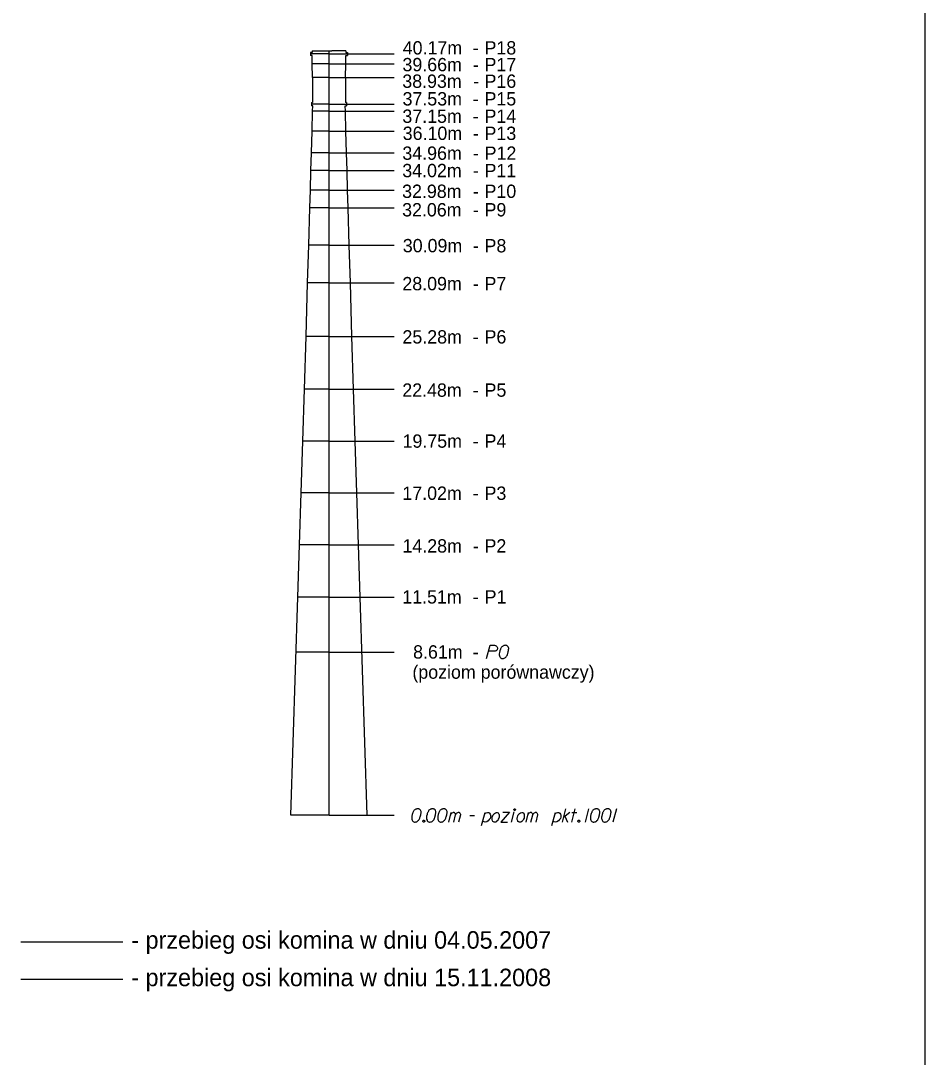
# Model space of a CAD drawing. Extents: x 138 to 6653, y -177 to 1520.
# Drawn here: x 387.54 to 398.01, y -57.33 to -45.34 of the extents above; entities that cross this region are included whole.
import ezdxf

# ---------------------------------------------------------------- set-up
doc = ezdxf.new("R2010")
doc.units = 0
for name, color, linetype in [('15 listopad 2008', 7, 'Continuous'), ('Opisy', 7, 'Continuous'), ('Ramka do drukowania', 7, 'Continuous')]:
    doc.layers.add(name, color=color, linetype=linetype)

msp = doc.modelspace()

# ---------------------------------------------------------------- linework, layer by layer
at = {"layer": '15 listopad 2008'}
for p, q in [((387.538, -55.997), (388.719, -55.997)), ((387.538, -56.429), (388.719, -56.429))]:
    msp.add_line(p, q, dxfattribs=at)
at = {"layer": 'Opisy'}
for p, q in [((390.893, -45.703), (390.893, -45.721)), ((390.91, -45.703), (390.893, -45.703)), ((390.91, -45.684), (390.91, -45.703)), ((390.91, -45.684), (391.137, -45.684)), ((391.106, -54.531), (391.106, -45.684)), ((391.302, -45.684), (391.137, -45.684)), ((391.302, -45.684), (391.302, -45.703)), ((391.302, -45.703), (391.319, -45.703)), ((391.319, -45.703), (391.319, -45.721)), ((391.106, -45.721), (390.893, -45.721)), ((390.893, -45.721), (390.893, -45.74)), ((390.91, -45.74), (390.893, -45.74)), ((390.91, -45.834), (390.91, -45.74)), ((391.106, -45.721), (391.859, -45.721)), ((391.302, -45.74), (391.319, -45.74)), ((391.302, -45.834), (391.302, -45.74)), ((391.319, -45.721), (391.319, -45.74)), ((391.106, -45.834), (390.91, -45.834)), ((390.916, -45.994), (390.91, -45.834)), ((391.106, -45.834), (391.859, -45.834)), ((391.296, -45.994), (391.302, -45.834)), ((391.106, -45.994), (390.916, -45.994)), ((390.916, -45.994), (390.916, -46.282)), ((391.106, -45.994), (391.859, -45.994)), ((391.296, -45.994), (391.296, -46.282)), ((390.903, -46.282), (390.903, -46.301)), ((390.903, -46.282), (390.916, -46.282)), ((391.106, -46.301), (390.903, -46.301)), ((390.903, -46.301), (390.903, -46.321)), ((391.106, -46.301), (391.859, -46.301)), ((391.309, -46.282), (391.296, -46.282)), ((391.309, -46.282), (391.309, -46.301)), ((391.309, -46.301), (391.309, -46.321)), ((390.918, -46.321), (390.903, -46.321)), ((390.91, -46.615), (390.916, -46.384)), ((390.916, -46.384), (390.918, -46.321)), ((391.106, -46.384), (390.916, -46.384)), ((391.106, -46.384), (391.859, -46.384)), ((391.296, -46.384), (391.294, -46.321)), ((391.294, -46.321), (391.309, -46.321)), ((391.302, -46.615), (391.296, -46.384)), ((390.903, -46.866), (390.91, -46.615)), ((391.106, -46.615), (390.91, -46.615)), ((391.106, -46.615), (391.859, -46.615)), ((391.309, -46.866), (391.302, -46.615)), ((390.897, -47.071), (390.903, -46.866)), ((391.106, -46.866), (390.903, -46.866)), ((391.106, -46.866), (391.859, -46.866)), ((391.315, -47.071), (391.309, -46.866)), ((390.891, -47.299), (390.897, -47.071)), ((391.106, -47.071), (390.897, -47.071)), ((391.106, -47.071), (391.859, -47.071)), ((391.321, -47.299), (391.315, -47.071)), ((390.884, -47.501), (390.891, -47.299)), ((391.106, -47.299), (390.891, -47.299)), ((391.106, -47.299), (391.859, -47.299)), ((391.329, -47.501), (391.321, -47.299)), ((390.871, -47.933), (390.884, -47.501)), ((391.106, -47.501), (390.884, -47.501)), ((391.106, -47.501), (391.859, -47.501)), ((391.341, -47.933), (391.329, -47.501)), ((390.858, -48.371), (390.871, -47.933)), ((391.106, -47.933), (390.871, -47.933)), ((391.106, -47.933), (391.859, -47.933)), ((391.354, -48.371), (391.341, -47.933)), ((390.841, -48.989), (390.858, -48.371)), ((391.106, -48.371), (390.858, -48.371)), ((391.106, -48.371), (391.859, -48.371)), ((391.371, -48.989), (391.354, -48.371)), ((390.821, -49.601), (390.841, -48.989)), ((391.106, -48.989), (390.841, -48.989)), ((391.106, -48.989), (391.859, -48.989)), ((391.391, -49.601), (391.371, -48.989)), ((390.802, -50.2), (390.821, -49.601)), ((391.106, -49.601), (390.821, -49.601)), ((391.106, -49.601), (391.859, -49.601)), ((391.41, -50.2), (391.391, -49.601)), ((390.784, -50.798), (390.802, -50.2)), ((391.106, -50.2), (390.802, -50.2)), ((391.106, -50.2), (391.859, -50.2)), ((391.428, -50.798), (391.41, -50.2)), ((390.765, -51.4), (390.784, -50.798)), ((391.106, -50.798), (390.784, -50.798)), ((391.106, -50.798), (391.859, -50.798)), ((391.447, -51.4), (391.428, -50.798)), ((390.745, -52.006), (390.765, -51.4)), ((391.106, -51.4), (390.765, -51.4)), ((391.106, -51.4), (391.859, -51.4)), ((391.467, -52.006), (391.447, -51.4)), ((390.663, -54.531), (390.745, -52.006)), ((391.106, -52.006), (390.745, -52.006)), ((391.106, -52.006), (391.859, -52.006)), ((391.549, -54.531), (391.467, -52.006)), ((391.106, -52.643), (390.725, -52.643)), ((391.106, -52.643), (391.859, -52.643)), ((391.106, -54.531), (390.663, -54.531)), ((391.106, -54.531), (391.859, -54.531))]:
    msp.add_line(p, q, dxfattribs=at)
for points in [[(392.928, -52.718), (392.97, -52.563), (393.022, -52.563), (393.029, -52.565), (393.033, -52.566), (393.04, -52.57), (393.045, -52.573), (393.048, -52.578), (393.052, -52.584), (393.055, -52.593), (393.056, -52.6), (393.055, -52.606), (393.053, -52.611), (393.051, -52.616), (393.048, -52.619), (393.045, -52.624), (393.04, -52.628), (393.036, -52.63), (393.03, -52.633), (393.024, -52.634), (392.951, -52.634)], [(393.149, -52.563), (393.147, -52.563), (393.14, -52.565), (393.135, -52.566), (393.131, -52.567), (393.125, -52.57), (393.118, -52.573), (393.112, -52.577), (393.106, -52.582), (393.102, -52.587), (393.098, -52.593), (393.095, -52.599), (393.091, -52.606), (393.089, -52.611), (393.086, -52.618), (393.082, -52.63), (393.079, -52.648), (393.076, -52.663), (393.076, -52.676), (393.078, -52.686), (393.082, -52.697), (393.086, -52.703), (393.092, -52.71), (393.099, -52.715), (393.103, -52.716), (393.11, -52.718), (393.116, -52.718), (393.126, -52.716), (393.135, -52.714), (393.141, -52.71), (393.149, -52.704), (393.153, -52.701), (393.158, -52.696), (393.161, -52.691), (393.164, -52.687), (393.166, -52.681), (393.167, -52.679), (393.17, -52.673), (393.172, -52.665), (393.175, -52.658), (393.176, -52.653), (393.177, -52.65), (393.178, -52.645), (393.181, -52.634), (393.182, -52.628), (393.183, -52.622), (393.184, -52.613), (393.186, -52.602), (393.186, -52.599), (393.184, -52.594), (393.183, -52.589), (393.18, -52.582), (393.176, -52.577), (393.172, -52.573), (393.167, -52.57), (393.163, -52.567), (393.159, -52.566), (393.155, -52.565), (393.149, -52.563)], [(392.135, -54.456), (392.133, -54.456), (392.126, -54.457), (392.121, -54.458), (392.117, -54.46), (392.111, -54.462), (392.104, -54.466), (392.098, -54.469), (392.092, -54.474), (392.088, -54.479), (392.084, -54.485), (392.081, -54.491), (392.077, -54.498), (392.075, -54.503), (392.072, -54.51), (392.069, -54.523), (392.065, -54.541), (392.063, -54.555), (392.063, -54.569), (392.064, -54.578), (392.069, -54.589), (392.072, -54.595), (392.078, -54.603), (392.086, -54.608), (392.089, -54.609), (392.097, -54.61), (392.103, -54.61), (392.112, -54.609), (392.121, -54.606), (392.127, -54.603), (392.135, -54.597), (392.139, -54.593), (392.144, -54.588), (392.147, -54.583), (392.15, -54.58), (392.152, -54.574), (392.154, -54.571), (392.156, -54.565), (392.158, -54.558), (392.161, -54.551), (392.162, -54.546), (392.163, -54.542), (392.164, -54.537), (392.167, -54.526), (392.168, -54.52), (392.169, -54.514), (392.171, -54.506), (392.172, -54.495), (392.172, -54.491), (392.171, -54.486), (392.169, -54.481), (392.166, -54.474), (392.162, -54.469), (392.158, -54.466), (392.154, -54.462), (392.149, -54.46), (392.145, -54.458), (392.141, -54.457), (392.135, -54.456)], [(392.306, -54.456), (392.304, -54.456), (392.297, -54.457), (392.292, -54.458), (392.288, -54.46), (392.282, -54.462), (392.275, -54.466), (392.269, -54.469), (392.263, -54.474), (392.259, -54.479), (392.256, -54.485), (392.252, -54.491), (392.248, -54.498), (392.246, -54.503), (392.243, -54.51), (392.24, -54.523), (392.236, -54.541), (392.234, -54.555), (392.234, -54.569), (392.235, -54.578), (392.24, -54.589), (392.243, -54.595), (392.249, -54.603), (392.257, -54.608), (392.26, -54.609), (392.268, -54.61), (392.274, -54.61), (392.283, -54.609), (392.292, -54.606), (392.298, -54.603), (392.306, -54.597), (392.31, -54.593), (392.315, -54.588), (392.319, -54.583), (392.321, -54.58), (392.323, -54.574), (392.325, -54.571), (392.327, -54.565), (392.33, -54.558), (392.332, -54.551), (392.333, -54.546), (392.334, -54.542), (392.336, -54.537), (392.338, -54.526), (392.339, -54.52), (392.34, -54.514), (392.342, -54.506), (392.343, -54.495), (392.343, -54.491), (392.342, -54.486), (392.34, -54.481), (392.337, -54.474), (392.333, -54.469), (392.33, -54.466), (392.325, -54.462), (392.32, -54.46), (392.316, -54.458), (392.313, -54.457), (392.306, -54.456)], [(392.436, -54.456), (392.434, -54.456), (392.427, -54.457), (392.422, -54.458), (392.418, -54.46), (392.412, -54.462), (392.405, -54.466), (392.399, -54.469), (392.393, -54.474), (392.389, -54.479), (392.385, -54.485), (392.382, -54.491), (392.378, -54.498), (392.376, -54.503), (392.373, -54.51), (392.37, -54.523), (392.366, -54.541), (392.364, -54.555), (392.364, -54.569), (392.365, -54.578), (392.37, -54.589), (392.373, -54.595), (392.379, -54.603), (392.387, -54.608), (392.39, -54.609), (392.398, -54.61), (392.404, -54.61), (392.413, -54.609), (392.422, -54.606), (392.428, -54.603), (392.436, -54.597), (392.44, -54.593), (392.445, -54.588), (392.448, -54.583), (392.451, -54.58), (392.453, -54.574), (392.455, -54.571), (392.457, -54.565), (392.459, -54.558), (392.462, -54.551), (392.463, -54.546), (392.464, -54.542), (392.465, -54.537), (392.468, -54.526), (392.469, -54.52), (392.47, -54.514), (392.472, -54.506), (392.473, -54.495), (392.473, -54.491), (392.472, -54.486), (392.47, -54.481), (392.467, -54.474), (392.463, -54.469), (392.459, -54.466), (392.455, -54.462), (392.45, -54.46), (392.446, -54.458), (392.442, -54.457), (392.436, -54.456)], [(393.251, -54.456), (393.257, -54.456), (393.261, -54.458), (393.264, -54.463), (393.264, -54.469), (393.261, -54.474), (393.257, -54.477), (393.251, -54.477), (393.247, -54.474), (393.244, -54.469), (393.244, -54.463), (393.247, -54.458), (393.251, -54.456)], [(393.807, -54.61), (393.848, -54.456)], [(393.915, -54.61), (393.955, -54.456)], [(394.11, -54.456), (394.069, -54.61)], [(394.204, -54.456), (394.201, -54.456), (394.194, -54.457), (394.189, -54.458), (394.186, -54.46), (394.18, -54.462), (394.172, -54.466), (394.166, -54.469), (394.16, -54.474), (394.156, -54.479), (394.153, -54.485), (394.149, -54.491), (394.146, -54.498), (394.143, -54.503), (394.141, -54.51), (394.137, -54.523), (394.133, -54.541), (394.131, -54.555), (394.131, -54.569), (394.132, -54.578), (394.137, -54.589), (394.141, -54.595), (394.147, -54.603), (394.154, -54.608), (394.158, -54.609), (394.165, -54.61), (394.171, -54.61), (394.181, -54.609), (394.189, -54.606), (394.195, -54.603), (394.204, -54.597), (394.207, -54.593), (394.212, -54.588), (394.216, -54.583), (394.218, -54.58), (394.221, -54.574), (394.222, -54.571), (394.224, -54.565), (394.227, -54.558), (394.229, -54.551), (394.231, -54.546), (394.232, -54.542), (394.233, -54.537), (394.235, -54.526), (394.237, -54.52), (394.238, -54.514), (394.239, -54.506), (394.24, -54.495), (394.24, -54.491), (394.239, -54.486), (394.238, -54.481), (394.234, -54.474), (394.231, -54.469), (394.227, -54.466), (394.222, -54.462), (394.217, -54.46), (394.214, -54.458), (394.21, -54.457), (394.204, -54.456)], [(394.334, -54.456), (394.331, -54.456), (394.324, -54.457), (394.319, -54.458), (394.315, -54.46), (394.309, -54.462), (394.302, -54.466), (394.296, -54.469), (394.29, -54.474), (394.286, -54.479), (394.283, -54.485), (394.279, -54.491), (394.275, -54.498), (394.273, -54.503), (394.271, -54.51), (394.267, -54.523), (394.263, -54.541), (394.261, -54.555), (394.261, -54.569), (394.262, -54.578), (394.267, -54.589), (394.271, -54.595), (394.277, -54.603), (394.284, -54.608), (394.288, -54.609), (394.295, -54.61), (394.301, -54.61), (394.311, -54.609), (394.319, -54.606), (394.325, -54.603), (394.334, -54.597), (394.337, -54.593), (394.342, -54.588), (394.346, -54.583), (394.348, -54.58), (394.351, -54.574), (394.352, -54.571), (394.354, -54.565), (394.357, -54.558), (394.359, -54.551), (394.36, -54.546), (394.362, -54.542), (394.363, -54.537), (394.365, -54.526), (394.366, -54.52), (394.368, -54.514), (394.369, -54.506), (394.37, -54.495), (394.37, -54.491), (394.369, -54.486), (394.368, -54.481), (394.364, -54.474), (394.36, -54.469), (394.357, -54.466), (394.352, -54.462), (394.347, -54.46), (394.343, -54.458), (394.34, -54.457), (394.334, -54.456)], [(394.432, -54.456), (394.391, -54.61)], [(392.493, -54.61), (392.521, -54.5)], [(392.514, -54.529), (392.52, -54.515), (392.526, -54.508), (392.533, -54.503), (392.541, -54.5), (392.546, -54.497), (392.553, -54.497), (392.555, -54.498), (392.56, -54.503), (392.565, -54.509), (392.569, -54.52), (392.57, -54.526), (392.576, -54.515), (392.583, -54.508), (392.591, -54.503), (392.598, -54.5), (392.604, -54.497), (392.61, -54.497), (392.615, -54.498), (392.618, -54.503), (392.622, -54.509), (392.626, -54.52), (392.627, -54.526), (392.606, -54.61)], [(392.549, -54.61), (392.57, -54.526)], [(392.736, -54.532), (392.789, -54.532)], [(392.871, -54.65), (392.912, -54.498)], [(392.909, -54.512), (392.921, -54.502), (392.939, -54.498), (392.954, -54.501), (392.963, -54.508), (392.971, -54.518), (392.975, -54.531), (392.977, -54.543), (392.974, -54.554), (392.971, -54.568), (392.961, -54.582), (392.949, -54.595), (392.931, -54.608), (392.915, -54.61), (392.9, -54.609), (392.884, -54.6)], [(393.045, -54.498), (393.053, -54.498), (393.063, -54.503), (393.073, -54.517), (393.074, -54.523), (393.075, -54.529), (393.075, -54.534), (393.075, -54.552), (393.071, -54.564), (393.065, -54.578), (393.058, -54.591), (393.046, -54.602), (393.035, -54.61), (393.017, -54.61), (393.009, -54.608), (393.002, -54.602), (392.998, -54.595), (392.994, -54.581), (392.994, -54.559), (392.996, -54.552), (393.001, -54.536), (393.006, -54.527), (393.008, -54.523), (393.02, -54.509), (393.032, -54.502), (393.045, -54.498)], [(393.117, -54.496), (393.196, -54.496), (393.096, -54.61), (393.173, -54.61)], [(393.217, -54.61), (393.249, -54.492)], [(393.336, -54.498), (393.344, -54.498), (393.354, -54.503), (393.364, -54.517), (393.365, -54.523), (393.366, -54.529), (393.366, -54.534), (393.366, -54.552), (393.363, -54.564), (393.357, -54.578), (393.349, -54.591), (393.337, -54.602), (393.326, -54.61), (393.308, -54.61), (393.301, -54.608), (393.293, -54.602), (393.29, -54.595), (393.285, -54.581), (393.285, -54.559), (393.287, -54.552), (393.292, -54.536), (393.297, -54.527), (393.3, -54.523), (393.312, -54.509), (393.324, -54.502), (393.336, -54.498)], [(393.387, -54.61), (393.415, -54.5)], [(393.408, -54.529), (393.414, -54.515), (393.42, -54.508), (393.427, -54.503), (393.434, -54.5), (393.439, -54.497), (393.446, -54.497), (393.449, -54.498), (393.454, -54.503), (393.459, -54.509), (393.462, -54.52), (393.463, -54.526), (393.469, -54.515), (393.477, -54.508), (393.484, -54.503), (393.491, -54.5), (393.497, -54.497), (393.503, -54.497), (393.508, -54.498), (393.512, -54.503), (393.516, -54.509), (393.519, -54.52), (393.52, -54.526), (393.5, -54.61)], [(393.443, -54.61), (393.463, -54.526)], [(393.684, -54.65), (393.726, -54.498)], [(393.722, -54.512), (393.734, -54.502), (393.752, -54.498), (393.767, -54.501), (393.777, -54.508), (393.784, -54.518), (393.789, -54.531), (393.79, -54.543), (393.788, -54.554), (393.784, -54.568), (393.774, -54.582), (393.762, -54.595), (393.744, -54.608), (393.728, -54.61), (393.713, -54.609), (393.698, -54.6)], [(393.821, -54.555), (393.894, -54.495)], [(393.836, -54.543), (393.868, -54.61)], [(393.915, -54.498), (393.973, -54.498)], [(392.2, -54.589), (392.206, -54.589), (392.209, -54.592), (392.213, -54.597), (392.213, -54.603), (392.209, -54.608), (392.206, -54.61), (392.2, -54.61), (392.196, -54.608), (392.192, -54.603), (392.192, -54.597), (392.196, -54.592), (392.2, -54.589)], [(393.994, -54.589), (394, -54.589), (394.004, -54.592), (394.007, -54.597), (394.007, -54.603), (394.004, -54.608), (394, -54.61), (393.994, -54.61), (393.99, -54.608), (393.987, -54.603), (393.987, -54.597), (393.99, -54.592), (393.994, -54.589)]]:
    msp.add_lwpolyline(points, dxfattribs=at)
at = {"layer": 'Ramka do drukowania'}
msp.add_line((398.007, -63.621), (398.007, -33.921), dxfattribs=at)

# ---------------------------------------------------------------- texts
at = {"layer": 'Opisy'}
for s, height, p in [('40.17m', 0.1542, (391.959, -45.727)), ('P18', 0.1542, (392.906, -45.727)), ('-', 0.154, (392.769, -45.727)), ('39.66m', 0.1542, (391.956, -45.921)), ('P17', 0.1542, (392.906, -45.921)), ('-', 0.154, (392.77, -45.921)), ('38.93m', 0.1542, (391.954, -46.113)), ('-', 0.154, (392.773, -46.113)), ('P16', 0.1542, (392.906, -46.113)), ('37.53m', 0.1542, (391.957, -46.317)), ('P15', 0.1542, (392.906, -46.317)), ('-', 0.154, (392.769, -46.317)), ('37.15m', 0.1542, (391.955, -46.518)), ('P14', 0.1542, (392.906, -46.518)), ('-', 0.154, (392.769, -46.518)), ('36.10m', 0.1542, (391.959, -46.716)), ('-', 0.154, (392.77, -46.716)), ('P13', 0.1542, (392.906, -46.716)), ('34.96m', 0.1542, (391.955, -46.946)), ('-', 0.154, (392.77, -46.946)), ('P12', 0.1542, (392.907, -46.946)), ('34.02m', 0.1542, (391.954, -47.147)), ('P11', 0.1542, (392.906, -47.147)), ('-', 0.154, (392.77, -47.147)), ('32.98m', 0.1542, (391.952, -47.387)), ('P10', 0.1542, (392.906, -47.387)), ('-', 0.154, (392.77, -47.387)), ('32.06m', 0.1542, (391.952, -47.601)), ('P9', 0.1542, (392.906, -47.601)), ('-', 0.154, (392.77, -47.601)), ('30.09m', 0.1542, (391.96, -48.016)), ('P8', 0.1542, (392.906, -48.017)), ('-', 0.154, (392.77, -48.016)), ('28.09m', 0.1542, (391.955, -48.456)), ('P7', 0.1542, (392.906, -48.456)), ('-', 0.154, (392.77, -48.456)), ('25.28m', 0.1542, (391.956, -49.072)), ('P6', 0.1542, (392.906, -49.072)), ('-', 0.154, (392.769, -49.072)), ('22.48m', 0.1542, (391.954, -49.688)), ('P5', 0.1542, (392.906, -49.688)), ('-', 0.154, (392.769, -49.688)), ('19.75m', 0.1542, (391.957, -50.278)), ('P4', 0.1542, (392.906, -50.278)), ('-', 0.154, (392.769, -50.278)), ('17.02m', 0.1542, (391.955, -50.881)), ('P3', 0.1542, (392.906, -50.881)), ('-', 0.154, (392.769, -50.881)), ('14.28m', 0.1542, (391.956, -51.491)), ('P2', 0.1542, (392.906, -51.491)), ('-', 0.154, (392.77, -51.491)), ('11.51m', 0.1542, (391.954, -52.081)), ('P1', 0.1542, (392.907, -52.081)), ('-', 0.154, (392.769, -52.081)), ('8.61m', 0.1542, (392.079, -52.718)), ('-', 0.154, (392.769, -52.718)), ('(poziom porównawczy)', 0.15416, (392.071, -52.951)), ('- przebieg osi komina w dniu 04.05.2007', 0.2024, (388.817, -56.075)), ('- przebieg osi komina w dniu 15.11.2008', 0.2024, (388.817, -56.509))]:
    msp.add_text(s, height=height, dxfattribs=at).set_placement(p)

doc.saveas('drawing.dxf')
